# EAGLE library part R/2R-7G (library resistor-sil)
R/2R Ladder 7 Murata RGSD14L
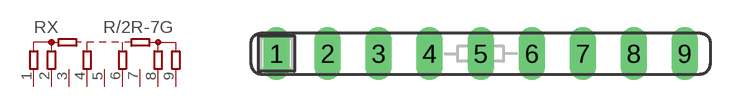
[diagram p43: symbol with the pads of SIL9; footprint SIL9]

Designator prefix RX

## R/2R-7G (OC_FARNELL: unknown; OC_NEWARK: unknown)  [SIL9]
1  IN  pas
2  B7  pas
3  B6  pas
4  B5  pas
5  B4  pas
6  B3  pas
7  B2  pas
8  B1  pas
9  OUT  pas

## Footprint SIL9 (pad centres in mm)
Single In Line
drill 0.813 long: 1 -10.16,0; 2 -7.62,0; 3 -5.08,0; 4 -2.54,0; 5 0,0; 6 2.54,0; 7 5.08,0; 8 7.62,0; 9 10.16,0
